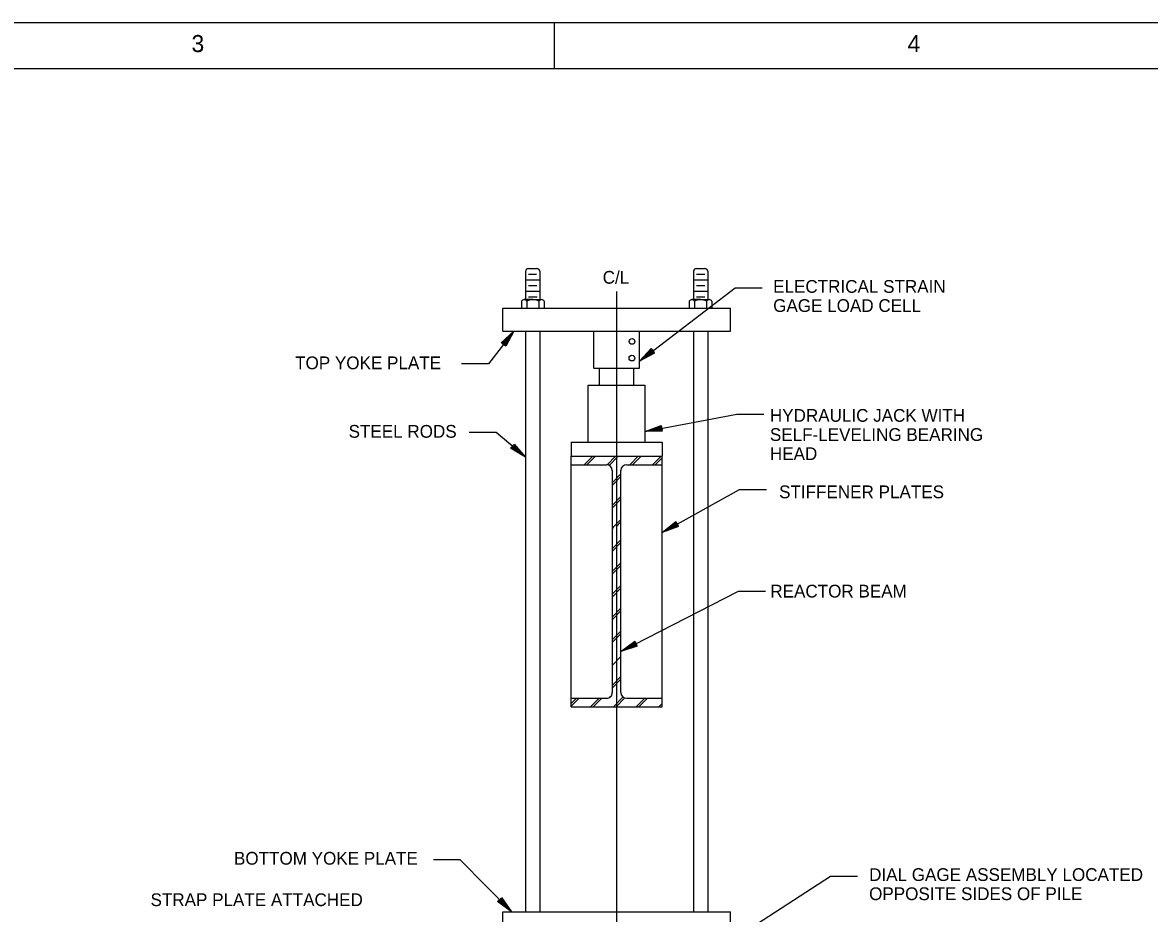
# Model space of a CAD drawing. Extents: x 22369.6 to 22413.6, y 22369.6 to 22403.6.
# Drawn here: x 22388.82 to 22401.19, y 22393.85 to 22403.63 of the extents above; entities that cross this region are included whole.
import ezdxf

# ---------------------------------------------------------------- set-up
doc = ezdxf.new("R2010")
doc.units = 0
for name, color, linetype in [('Level 1', 7, 'Continuous'), ('Level 10', 7, 'Continuous'), ('Level 2', 7, 'Continuous'), ('Level 4', 7, 'Continuous'), ('Level 7', 7, 'Continuous'), ('Level 9', 7, 'Continuous')]:
    doc.layers.add(name, color=color, linetype=linetype)

msp = doc.modelspace()

# ---------------------------------------------------------------- linework, layer by layer
at = {"layer": 'Level 1'}
for p, q in [((22394.377, 22400.867), (22394.466, 22400.867)), ((22396.221, 22400.867), (22396.313, 22400.867)), ((22394.344, 22400.804), (22394.5, 22400.804)), ((22394.376, 22400.742), (22394.468, 22400.742)), ((22396.187, 22400.804), (22396.344, 22400.804)), ((22396.221, 22400.742), (22396.313, 22400.742)), ((22394.344, 22400.679), (22394.5, 22400.679)), ((22394.375, 22400.617), (22394.47, 22400.617)), ((22395.344, 22400.675), (22395.344, 22389.526)), ((22396.187, 22400.679), (22396.344, 22400.679)), ((22396.221, 22400.617), (22396.313, 22400.617)), ((22394.3, 22400.571), (22394.3, 22400.493)), ((22394.3, 22400.493), (22394.55, 22400.493)), ((22394.329, 22400.587), (22394.52, 22400.587)), ((22394.425, 22400.587), (22394.329, 22400.587)), ((22394.358, 22400.571), (22394.358, 22400.493)), ((22394.491, 22400.571), (22394.491, 22400.493)), ((22394.55, 22400.571), (22394.55, 22400.493)), ((22396.14, 22400.572), (22396.14, 22400.494)), ((22396.14, 22400.494), (22396.39, 22400.494)), ((22396.17, 22400.587), (22396.361, 22400.587)), ((22396.265, 22400.587), (22396.17, 22400.587)), ((22396.199, 22400.572), (22396.199, 22400.494)), ((22396.332, 22400.572), (22396.332, 22400.494)), ((22396.39, 22400.572), (22396.39, 22400.494)), ((22394.217, 22400.242), (22394.217, 22400.242)), ((22394.185, 22400.201), (22394.185, 22400.201)), ((22395.594, 22399.912), (22395.594, 22399.912)), ((22395.635, 22399.943), (22395.635, 22399.943)), ((22395.656, 22399.14), (22395.656, 22399.14)), ((22395.707, 22399.149), (22395.707, 22399.149)), ((22394.304, 22398.892), (22394.304, 22398.892)), ((22394.344, 22398.859), (22394.344, 22398.859)), ((22394.988, 22398.773), (22395.082, 22398.867)), ((22395.018, 22398.773), (22395.112, 22398.867)), ((22395.239, 22398.773), (22395.332, 22398.867)), ((22395.261, 22398.766), (22395.362, 22398.867)), ((22395.489, 22398.773), (22395.582, 22398.867)), ((22395.518, 22398.773), (22395.612, 22398.867)), ((22395.739, 22398.773), (22395.832, 22398.867)), ((22395.768, 22398.773), (22395.843, 22398.849)), ((22395.297, 22398.581), (22395.39, 22398.675)), ((22395.297, 22398.552), (22395.39, 22398.646)), ((22395.297, 22398.331), (22395.39, 22398.425)), ((22395.297, 22398.302), (22395.39, 22398.396)), ((22395.308, 22398.092), (22395.39, 22398.175)), ((22395.337, 22398.092), (22395.39, 22398.146)), ((22395.297, 22398.076), (22395.313, 22398.092)), ((22395.844, 22398.032), (22395.844, 22398.032)), ((22395.297, 22397.856), (22395.39, 22397.949)), ((22395.297, 22397.826), (22395.39, 22397.92)), ((22395.297, 22397.606), (22395.39, 22397.699)), ((22395.297, 22397.576), (22395.39, 22397.67)), ((22395.297, 22397.356), (22395.39, 22397.449)), ((22395.297, 22397.326), (22395.39, 22397.42)), ((22395.297, 22397.106), (22395.39, 22397.199)), ((22395.297, 22397.076), (22395.39, 22397.17)), ((22395.297, 22396.856), (22395.39, 22396.949)), ((22395.297, 22396.826), (22395.39, 22396.92)), ((22395.297, 22396.576), (22395.39, 22396.67)), ((22395.39, 22396.725), (22395.39, 22396.725)), ((22395.297, 22396.356), (22395.39, 22396.449)), ((22395.297, 22396.326), (22395.39, 22396.42)), ((22394.844, 22396.153), (22394.902, 22396.211)), ((22394.844, 22396.123), (22394.931, 22396.211)), ((22395.058, 22396.117), (22395.152, 22396.211)), ((22395.087, 22396.117), (22395.181, 22396.211)), ((22395.308, 22396.117), (22395.416, 22396.225)), ((22395.337, 22396.117), (22395.435, 22396.214)), ((22395.558, 22396.117), (22395.652, 22396.211)), ((22395.587, 22396.117), (22395.681, 22396.211)), ((22395.808, 22396.117), (22395.844, 22396.153)), ((22394.154, 22393.904), (22394.154, 22393.904)), ((22394.19, 22393.867), (22394.19, 22393.867))]:
    msp.add_line(p, q, dxfattribs=at)
msp.add_lwpolyline([(22369.621, 22403.629), (22413.622, 22403.629), (22413.622, 22369.621), (22369.621, 22369.621)], close=True, dxfattribs=at)
for points in [[(22395.594, 22399.912), (22396.646, 22400.718), (22396.942, 22400.718)], [(22394.217, 22400.242), (22393.938, 22399.881), (22393.642, 22399.881)], [(22394.078, 22400.113), (22394.217, 22400.242), (22394.127, 22400.075), (22394.085, 22400.107), (22394.185, 22400.201), (22394.124, 22400.087), (22394.097, 22400.108), (22394.155, 22400.161), (22394.121, 22400.1), (22394.11, 22400.108), (22394.123, 22400.12)], [(22395.761, 22400.001), (22395.594, 22399.912), (22395.723, 22400.05), (22395.755, 22400.008), (22395.635, 22399.943), (22395.723, 22400.037), (22395.744, 22400.01), (22395.674, 22399.974), (22395.723, 22400.024), (22395.731, 22400.013), (22395.716, 22400.005)], [(22395.656, 22399.14), (22396.662, 22399.329), (22396.958, 22399.329)], [(22394.344, 22398.859), (22394.021, 22399.127), (22393.725, 22399.127)], [(22395.846, 22399.144), (22395.656, 22399.14), (22395.834, 22399.205), (22395.844, 22399.153), (22395.707, 22399.149), (22395.828, 22399.193), (22395.834, 22399.16), (22395.756, 22399.159), (22395.822, 22399.182), (22395.825, 22399.168), (22395.807, 22399.168)], [(22394.22, 22399.002), (22394.344, 22398.859), (22394.18, 22398.955), (22394.214, 22398.995), (22394.304, 22398.892), (22394.192, 22398.957), (22394.214, 22398.983), (22394.265, 22398.924), (22394.205, 22398.96), (22394.214, 22398.971), (22394.225, 22398.957)], [(22395.844, 22398.032), (22396.693, 22398.501), (22396.99, 22398.501)], [(22396.022, 22398.095), (22395.844, 22398.032), (22395.992, 22398.15), (22396.018, 22398.103), (22395.889, 22398.057), (22395.99, 22398.137), (22396.007, 22398.107), (22395.933, 22398.081), (22395.988, 22398.124), (22395.995, 22398.112), (22395.978, 22398.106)], [(22395.39, 22396.725), (22396.683, 22397.386), (22396.979, 22397.386)], [(22395.571, 22396.783), (22395.39, 22396.725), (22395.543, 22396.838), (22395.567, 22396.791), (22395.437, 22396.749), (22395.54, 22396.825), (22395.556, 22396.795), (22395.481, 22396.772), (22395.538, 22396.813), (22395.544, 22396.8), (22395.528, 22396.795)], [(22394.19, 22393.867), (22393.628, 22394.438), (22393.332, 22394.438)], [(22395.537, 22392.86), (22397.693, 22394.257), (22397.989, 22394.257)], [(22394.081, 22394.022), (22394.19, 22393.867), (22394.037, 22393.978), (22394.075, 22394.016), (22394.154, 22393.904), (22394.05, 22393.98), (22394.074, 22394.004), (22394.119, 22393.94), (22394.063, 22393.981), (22394.073, 22393.991), (22394.082, 22393.977)]]:
    msp.add_lwpolyline(points, dxfattribs=at)
msp.add_circle((22395.512, 22399.945), 0.0313, dxfattribs=at)
for centre, radius, start, end in [((22394.329, 22400.552), 0.0352, 33.7684, 146.2316), ((22394.425, 22400.438), 0.149, 63.517, 116.483), ((22394.52, 22400.552), 0.0352, 33.7599, 146.2401), ((22396.17, 22400.552), 0.0352, 33.7684, 146.2316), ((22396.265, 22400.438), 0.149, 63.517, 116.483), ((22396.361, 22400.552), 0.0352, 33.7599, 146.2401)]:
    msp.add_arc(centre, radius, start, end, dxfattribs=at)
msp.add_ellipse((22395.513, 22400.128), major_axis=(0.0312, 0), ratio=0.999666, dxfattribs=at)
at = {"layer": 'Level 10'}
msp.add_line((22394.662, 22403.125), (22394.662, 22403.629), dxfattribs=at)
at = {"layer": 'Level 2'}
for p, q in [((22394.344, 22400.898), (22394.344, 22400.584)), ((22394.375, 22400.929), (22394.469, 22400.929)), ((22394.5, 22400.898), (22394.5, 22400.585)), ((22396.187, 22400.898), (22396.187, 22400.586)), ((22396.219, 22400.929), (22396.312, 22400.929)), ((22396.344, 22400.898), (22396.344, 22400.587)), ((22394.344, 22400.242), (22394.344, 22393.867)), ((22394.5, 22400.242), (22394.5, 22393.867)), ((22396.187, 22400.242), (22396.187, 22393.867)), ((22396.344, 22400.242), (22396.344, 22393.867)), ((22394.844, 22396.117), (22394.844, 22398.867)), ((22394.844, 22398.773), (22395.234, 22398.773)), ((22395.453, 22398.773), (22395.844, 22398.773)), ((22395.844, 22396.117), (22395.844, 22398.867)), ((22395.297, 22396.273), (22395.297, 22398.711)), ((22395.39, 22396.273), (22395.39, 22398.711)), ((22395.889, 22398.057), (22395.889, 22398.057)), ((22395.437, 22396.749), (22395.437, 22396.749)), ((22394.844, 22396.211), (22395.234, 22396.211)), ((22395.453, 22396.211), (22395.844, 22396.211)), ((22394.844, 22396.117), (22395.844, 22396.117))]:
    msp.add_line(p, q, dxfattribs=at)
for centre, radius, start, end in [((22394.375, 22400.898), 0.0311, 89.8555, 180.3164), ((22394.468, 22400.898), 0.0314, 0.1075, 89.7206), ((22396.219, 22400.898), 0.0313, 89.9906, 179.9903), ((22396.312, 22400.898), 0.0313, 0.0097, 90.0094), ((22395.234, 22398.711), 0.0625, 0.0046, 89.9954), ((22395.453, 22398.711), 0.0625, 90.0209, 179.9791), ((22395.234, 22396.273), 0.0625, 269.9883, 0.0117), ((22395.453, 22396.273), 0.0625, 180.0046, 269.9954)]:
    msp.add_arc(centre, radius, start, end, dxfattribs=at)
at = {"layer": 'Level 7'}
for p, q in [((22394.094, 22400.492), (22396.594, 22400.492)), ((22394.094, 22400.242), (22394.094, 22400.492)), ((22396.594, 22400.242), (22396.594, 22400.492)), ((22394.094, 22400.242), (22396.594, 22400.242)), ((22395.094, 22399.836), (22395.094, 22400.242)), ((22395.594, 22399.836), (22395.594, 22400.242)), ((22395.094, 22399.836), (22395.594, 22399.836)), ((22395.156, 22399.648), (22395.156, 22399.836)), ((22395.531, 22399.648), (22395.531, 22399.836)), ((22395.031, 22399.648), (22395.656, 22399.648)), ((22395.031, 22399.023), (22395.031, 22399.648)), ((22395.656, 22399.023), (22395.656, 22399.648)), ((22394.844, 22399.023), (22395.844, 22399.023)), ((22394.844, 22399.023), (22394.844, 22398.867)), ((22395.844, 22399.023), (22395.844, 22398.867)), ((22394.844, 22398.867), (22395.844, 22398.867)), ((22394.094, 22393.867), (22396.594, 22393.867)), ((22394.094, 22393.617), (22394.094, 22393.867)), ((22396.594, 22393.617), (22396.594, 22393.867))]:
    msp.add_line(p, q, dxfattribs=at)
at = {"layer": 'Level 9'}
msp.add_line((22371.121, 22403.125), (22410.37, 22403.125), dxfattribs=at)

# ---------------------------------------------------------------- texts
at = {"layer": 'Level 1'}
for s, p in [('3', (22390.678, 22403.305)), ('4', (22398.538, 22403.305))]:
    msp.add_text(s, height=0.187, dxfattribs=at).set_placement(p)
at = {"layer": 'Level 4'}
for s, p in [('C/L', (22395.191, 22400.762)), ('ELECTRICAL STRAIN', (22397.062, 22400.662)), ('GAGE LOAD CELL', (22397.062, 22400.452)), ('TOP YOKE PLATE', (22391.815, 22399.823)), ('HYDRAULIC JACK WITH', (22397.026, 22399.246)), ('STEEL RODS', (22392.402, 22399.071)), ('SELF-LEVELING BEARING', (22397.026, 22399.036)), ('HEAD', (22397.026, 22398.826)), ('STIFFENER PLATES', (22397.127, 22398.407)), ('REACTOR BEAM', (22397.031, 22397.317)), ('BOTTOM YOKE PLATE', (22391.144, 22394.384)), ('DIAL GAGE ASSEMBLY LOCATED', (22398.115, 22394.205)), ('STRAP PLATE ATTACHED', (22390.228, 22393.929)), ('OPPOSITE SIDES OF PILE', (22398.115, 22393.995))]:
    msp.add_text(s, height=0.14, dxfattribs=at).set_placement(p)

doc.saveas('drawing.dxf')
